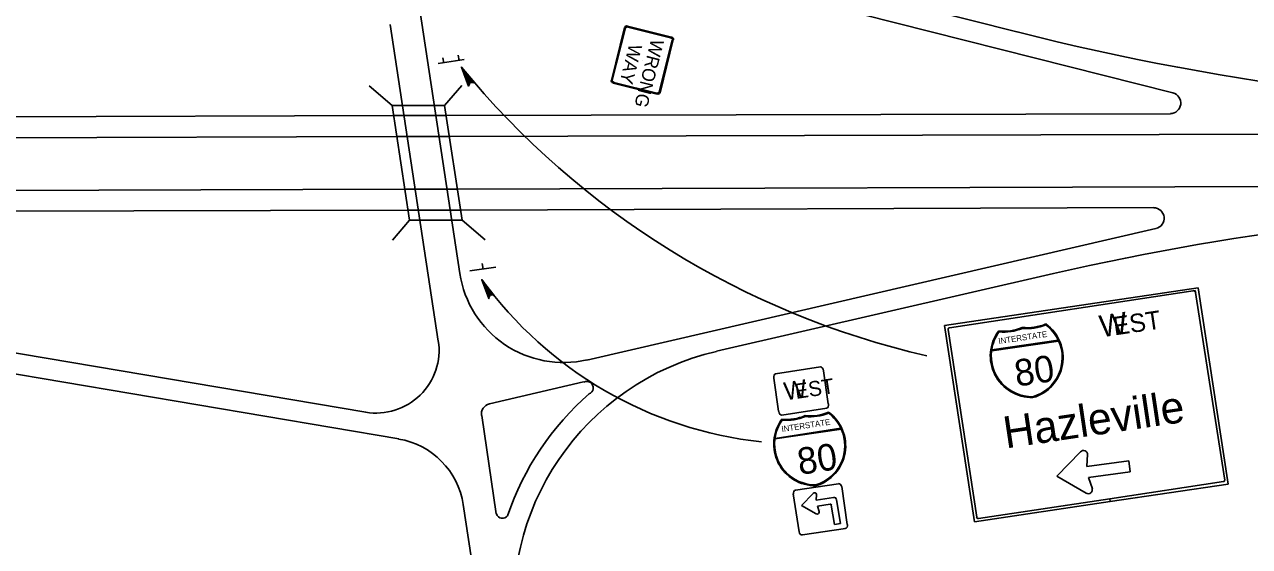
# Model space of a CAD drawing. Extents: x 644898 to 648326, y 298294 to 300670.
# Drawn here: x 646894.3 to 647208.5, y 300321.7 to 300455.8 of the extents above; entities that cross this region are included whole.
import ezdxf

# ---------------------------------------------------------------- set-up
doc = ezdxf.new("R2010")
doc.units = 0
doc.layers.add('2', color=7, linetype='Continuous')

msp = doc.modelspace()

# ---------------------------------------------------------------- linework, layer by layer
at = {"layer": '2'}
for p, q in [((647148.82, 300453.87), (647003.32, 300490.74)), ((647188.82, 300438.24), (647014.82, 300482.24)), ((646994.95, 300464.24), (647005.95, 300391.87)), ((646988.07, 300455.74), (647000.45, 300374.49)), ((647048.95, 300455.37), (647060.2, 300452.49)), ((647049.07, 300455.12), (647059.95, 300452.37)), ((647044.82, 300441.37), (647048.2, 300454.99)), ((647045.07, 300441.49), (647048.45, 300454.87)), ((647060.45, 300451.74), (647057.07, 300438.49)), ((647060.7, 300451.87), (647057.32, 300438.24)), ((647007.07, 300446.74), (647000.45, 300445.74)), ((647001.82, 300445.87), (647001.57, 300447.24)), ((647005.82, 300446.49), (647005.57, 300447.87)), ((647052.7, 300446.62), (647052.7, 300446.62)), ((646982.7, 300439.99), (646988.57, 300434.99)), ((647006.45, 300440.12), (647002.07, 300434.99)), ((647056.57, 300437.87), (647045.32, 300440.74)), ((647056.45, 300438.12), (647045.45, 300440.87)), ((646993.07, 300405.49), (646988.57, 300434.99)), ((646988.57, 300434.99), (647002.07, 300434.99)), ((647002.07, 300434.99), (647006.57, 300405.49)), ((646719.57, 300431.49), (646988.95, 300432.37)), ((646988.95, 300432.37), (647002.57, 300432.37)), ((646991.7, 300432.37), (646991.7, 300432.37)), ((646999.82, 300432.37), (646999.82, 300432.37)), ((647002.57, 300432.37), (647188.2, 300432.87)), ((646620.32, 300425.88), (646989.7, 300426.99)), ((646989.7, 300426.99), (647003.32, 300426.99)), ((647003.32, 300426.99), (647406.32, 300428.13)), ((647005.32, 300413.49), (647406.32, 300414.76)), ((646620.32, 300412.38), (646991.82, 300413.49)), ((646991.82, 300413.49), (647005.32, 300413.49)), ((646712.2, 300407.37), (646992.57, 300408.12)), ((646992.57, 300408.12), (647006.2, 300408.12)), ((646995.32, 300408.12), (646995.32, 300408.12)), ((647003.45, 300408.12), (647003.45, 300408.12)), ((647006.2, 300408.12), (647183.95, 300408.74)), ((646988.7, 300400.37), (646993.07, 300405.49)), ((647006.57, 300405.49), (646993.07, 300405.49)), ((647012.45, 300400.49), (647006.57, 300405.49)), ((646711.82, 300401.99), (646981.82, 300356.24)), ((647038.57, 300369.62), (647184.45, 300403.37)), ((646705.95, 300397.49), (646990.32, 300349.37)), ((647015.2, 300393.49), (647008.57, 300392.49)), ((647011.95, 300392.99), (647011.7, 300394.37)), ((647071.82, 300371.87), (647158.2, 300391.87)), ((647130.29, 300378.48), (647195.26, 300388.14)), ((647202.12, 300338.79), (647194.53, 300387.47)), ((647195.26, 300388.14), (647202.96, 300337.77)), ((647137.9, 300328.09), (647130.29, 300378.49)), ((647131.2, 300377.5), (647138.55, 300329.3)), ((647144.26, 300376.81), (647144.26, 300376.81)), ((647150.27, 300377.73), (647150.27, 300377.73)), ((647156.19, 300378.63), (647156.19, 300378.63)), ((647142.37, 300371.95), (647159.5, 300374.49)), ((647159.43, 300374.76), (647142.39, 300372.24)), ((647086.95, 300366.12), (647098.45, 300367.87)), ((647087.7, 300356.49), (647086.45, 300364.99)), ((647099.2, 300366.87), (647100.45, 300358.37)), ((647013.57, 300358.37), (647037.7, 300363.99)), ((647093.45, 300361.62), (647093.45, 300361.62)), ((647011.57, 300355.37), (647015.32, 300330.12)), ((647100.07, 300357.24), (647088.57, 300355.49)), ((647094.57, 300355.12), (647094.57, 300355.12)), ((647100.45, 300355.99), (647100.45, 300355.99)), ((647086.7, 300349.37), (647103.82, 300351.87)), ((647103.7, 300352.12), (647086.82, 300349.49)), ((647088.7, 300354.24), (647088.7, 300354.24)), ((647095.95, 300346.37), (647095.95, 300346.37)), ((647159.07, 300339.79), (647165.16, 300346.09)), ((647166.91, 300345.44), (647166.79, 300342.32)), ((647166.79, 300342.32), (647177.51, 300343.77)), ((647177.51, 300343.77), (647177.87, 300340.88)), ((647166.58, 300335.41), (647159.07, 300339.79)), ((647177.87, 300340.88), (647167.15, 300339.43)), ((647167.15, 300339.43), (647168.17, 300336.57)), ((647092.07, 300336.24), (647103.07, 300337.87)), ((647092.07, 300336.24), (647103.07, 300337.87)), ((647103.95, 300337.12), (647105.32, 300327.37)), ((647103.95, 300337.12), (647105.32, 300327.37)), ((647172.64, 300334), (647201.76, 300338.44)), ((647202.96, 300337.77), (647172.75, 300333.27)), ((647092.95, 300325.49), (647091.45, 300335.24)), ((647092.95, 300325.49), (647091.45, 300335.24)), ((647096.57, 300335.37), (647093.57, 300332.24)), ((647097.32, 300333.62), (647097.45, 300335.12)), ((647101.82, 300334.37), (647097.32, 300333.62)), ((647097.7, 300332.12), (647100.95, 300332.62)), ((647102.57, 300333.74), (647102.57, 300333.74)), ((647103.57, 300327.62), (647102.57, 300333.74)), ((647172.75, 300333.27), (647137.9, 300328.09)), ((647138.94, 300328.93), (647172.64, 300334)), ((647172.75, 300333.27), (647172.64, 300334)), ((647172.64, 300334), (647172.75, 300333.27)), ((647006.82, 300332.49), (647043.57, 300091.49)), ((647093.57, 300332.24), (647097.32, 300330.12)), ((647098.07, 300330.74), (647097.7, 300332.12)), ((647098.45, 300331.24), (647098.45, 300331.24)), ((647098.45, 300331.24), (647098.45, 300331.24)), ((647101.2, 300332.37), (647102.07, 300327.37)), ((647104.82, 300326.37), (647093.82, 300324.74)), ((647104.82, 300326.37), (647093.82, 300324.74)), ((647102.07, 300327.37), (647103.57, 300327.62))]:
    msp.add_line(p, q, dxfattribs=at)
for points in [[(647008.32, 300440.31), (647008.56, 300440.69), (647006.37, 300444.83), (647008.32, 300440.31), (647008.2, 300439.97), (647006.37, 300444.83), (647008.9, 300440.85), (647009.3, 300440.9), (647006.37, 300444.83), (647009.63, 300440.77), (647009.3, 300440.9)], [(647013.47, 300385.75), (647013.66, 300386.1), (647011.57, 300390.25), (647013.47, 300385.75), (647013.41, 300385.38), (647011.57, 300390.25), (647014.07, 300386.28), (647014.46, 300386.34), (647011.57, 300390.25), (647014.81, 300386.16), (647014.46, 300386.34)], [(647194.53, 300387.47), (647131.49, 300377.85)]]:
    msp.add_lwpolyline(points, dxfattribs=at)
for centre, radius, start, end in [((647313.92, 301105.15), 671.88, 255.77937, 270.1682), ((647174.23, 300581.99), 216.77, 219.2532, 257.0731), ((647188.16, 300435.59), 2.69, 270.1683, 75.7793), ((647309.55, 299737.19), 671.88, 90.1683, 103.0152), ((647183.9, 300406.01), 2.69, 283.0152, 90.1683), ((647032.54, 300395.85), 26.87, 188.6538, 283.0152), ((647094.45, 300450.26), 102.28, 215.9181, 263.7348), ((646984.5, 300372.13), 16.13, 260.3831, 8.6537), ((647086.94, 300306.37), 67.19, 103.0152, 188.6538), ((647038.49, 300362.47), 1.67, 290.9294, 117.2399), ((647086.94, 300306.37), 72.56, 131.1224, 161.2817), ((647014.18, 300355.75), 2.69, 103.0154, 188.6538), ((647089.74, 300366.7), 12.33, 264.4038, 292.9038), ((647089.74, 300366.7), 12.56, 264.9943, 292.6428), ((647095.74, 300367.61), 12.33, 264.4038, 292.9038), ((647095.74, 300367.61), 12.56, 264.6648, 292.3133), ((647094.18, 300347.61), 10.73, 286.7839, 53.6538), ((647094.18, 300347.61), 10.51, 25.4466, 52.9614), ((647097.18, 300348.07), 10.73, 143.6538, 270.5237), ((647097.18, 300348.07), 10.51, 144.3462, 171.8611), ((647094.18, 300347.61), 10.51, 286.7839, 24.1669), ((646986.91, 300329.47), 20.16, 8.6538, 80.3831), ((647097.18, 300348.07), 10.51, 173.1407, 270.5237), ((647096.91, 300335.08), 0.502, 358.1291, 138.7947), ((647100.98, 300332.36), 0.269, 8.6538, 98.6538), ((647101.92, 300333.68), 0.672, 8.6538, 98.6538), ((647016.91, 300330.62), 1.63, 197.7979, 323.4245), ((647097.62, 300330.59), 0.502, 236.4996, 20.4062)]:
    msp.add_arc(centre, radius, start, end, dxfattribs=at)
for centre, major_axis, ratio, start_param, end_param in [((647048.85, 300454.88), (-0.625, 0.158), 0.777833, 4.712389, 6.283185), ((647049, 300454.69), (-0.578, 0.147), 0.777833, 4.712389, 6.283185), ((647059.88, 300451.93), (-0.578, 0.147), 0.777833, 3.141593, 4.712389), ((647060.1, 300452.02), (-0.625, 0.158), 0.777833, 3.141593, 4.712389), ((647045.4, 300441.26), (0.625, -0.158), 0.777833, 3.141593, 4.712389), ((647045.62, 300441.36), (0.578, -0.147), 0.777833, 3.141593, 4.712389), ((647056.5, 300438.6), (0.578, -0.147), 0.777833, 4.712389, 6.283185), ((647056.65, 300438.41), (0.625, -0.158), 0.777833, 4.712389, 6.283185), ((647194.28, 300386.93), (-0.388, 0), 0.989072, 3.283634, 4.860778), ((647131.53, 300377.52), (-0.388, 0), 0.989072, 4.856969, 6.450662), ((647152.85, 300370.7), (-10.85, 0), 0.989072, 5.647198, 7.861496), ((647152.85, 300370.7), (-10.62, 0), 0.989072, 5.659282, 6.139508), ((647145.36, 300389.34), (-12.46, 0), 0.989072, 1.471498, 1.968918), ((647145.36, 300389.34), (-12.69, 0), 0.989072, 1.481804, 1.964361), ((647151.43, 300390.25), (12.46, 0), 0.989072, 4.61309, 5.11051), ((647151.43, 300390.25), (12.69, 0), 0.989072, 4.617647, 5.100204), ((647149.82, 300370.25), (10.85, 0), 0.989072, 5.003697, 7.217995), ((647149.82, 300370.25), (10.62, 0), 0.989072, 0.4425, 0.922725), ((647149.82, 300370.25), (10.62, 0), 0.989072, 5.003697, 6.703352), ((647152.85, 300370.7), (-10.62, 0), 0.989072, 6.161841, 7.861496), ((647098.58, 300366.79), (-0.16, 1.06), 0.6, 4.712389, 6.283185), ((647087.1, 300365.04), (0.16, -1.06), 0.6, 3.141593, 4.712389), ((647099.87, 300358.29), (-0.16, 1.06), 0.6, 3.141593, 4.712389), ((647088.4, 300356.54), (0.16, -1.06), 0.6, 4.712389, 6.283185), ((647165.9, 300345.4), (-1.03, 0), 0.989072, 3.073775, 5.58542), ((647092.2, 300335.3), (0.14, -0.921), 0.769266, 3.141593, 4.712389), ((647092.2, 300335.3), (0.14, -0.921), 0.769266, 3.141593, 4.712389), ((647103.19, 300336.98), (-0.14, 0.921), 0.769266, 4.712389, 6.283185), ((647103.19, 300336.98), (-0.14, 0.921), 0.769266, 4.712389, 6.283185), ((647167.12, 300336.3), (-1.03, 0), 0.989072, 1.007506, 3.462583), ((647201.73, 300338.74), (0.361, 0.041), 0.980329, 4.753008, 6.326457), ((647104.66, 300327.3), (-0.14, 0.921), 0.769266, 3.141593, 4.712389), ((647104.66, 300327.3), (-0.14, 0.921), 0.769266, 3.141593, 4.712389), ((647138.9, 300329.34), (-0.402, -0.077), 0.953585, 6.234444, 7.82518), ((647093.67, 300325.63), (0.14, -0.921), 0.769266, 4.712389, 6.283185), ((647093.67, 300325.63), (0.14, -0.921), 0.769266, 4.712389, 6.283185)]:
    msp.add_ellipse(centre, major_axis=major_axis, ratio=ratio, start_param=start_param, end_param=end_param, dxfattribs=at)

# ---------------------------------------------------------------- texts
for s, height, rotation, p in [('WAY', 3.386, 255.7793, (647049.45, 300450.99)), ('WRONG', 3.385, 255.7793, (647055.07, 300452.24)), ('W', 5.63, 8.4837, (647170.44, 300375.42)), ('EST', 4.719, 8.4705, (647173.85, 300375.93)), ('INTERSTATE', 1.517, 8.469, (647144.19, 300373.71)), ('80', 6.829, 8.468, (647148.73, 300362.78)), ('W', 4.63, 8.6525, (647089.45, 300359.24)), ('EST', 3.875, 8.6538, (647092.2, 300359.62)), ('Hazleville', 8.168, 8.4705, (647145.97, 300346.9)), ('INTERSTATE', 1.517, 8.6538, (647088.57, 300351.12)), ('80', 6.829, 8.6538, (647093.07, 300340.12))]:
    msp.add_text(s, height=height, rotation=rotation, dxfattribs=at).set_placement(p)

doc.saveas('drawing.dxf')
